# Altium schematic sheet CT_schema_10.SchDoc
size 281 x 153 mm
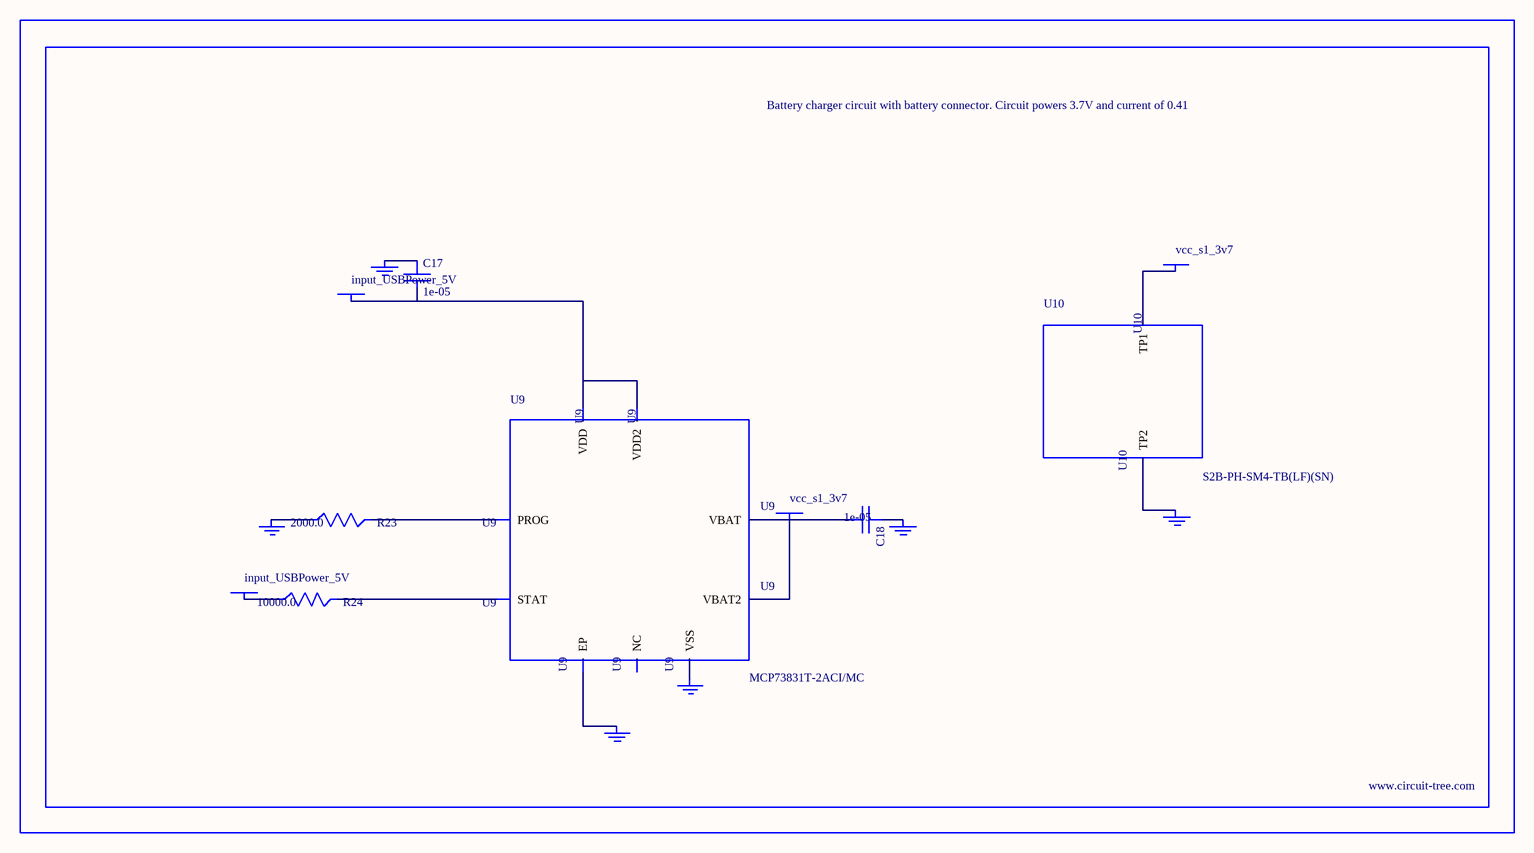
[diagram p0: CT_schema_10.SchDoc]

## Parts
BORDER9  (no value)
C17  1e-05  [C1206]
C18  1e-05  [C1206]
GND_INSTANCE_9_0  (no value)
GND_INSTANCE_9_1  (no value)
GND_INSTANCE_9_2  (no value)
GND_INSTANCE_9_3  (no value)
GND_INSTANCE_9_4  (no value)
GND_INSTANCE_9_5  (no value)
POWER_INSTANCE_9_0  input_USBPower_5V
POWER_INSTANCE_9_1  input_USBPower_5V
POWER_INSTANCE_9_2  vcc_s1_3v7
POWER_INSTANCE_9_3  vcc_s1_3v7
R23  2000.0  [R0603]
R24  10000.0  [R0603]
U9  MCP73831T-2ACI/MC  [DFN8_2X3MC]
U10  S2B-PH-SM4-TB(LF)(SN)  [JST-2-SMD]

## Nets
NetC17_1: C17.1 GND_INSTANCE_9_0.0(GND)
NetC17_2: C17.2 POWER_INSTANCE_9_0.0(PWR) U9.1(VDD) U9.2(VDD2)
NetC18_1: C18.1 GND_INSTANCE_9_1.0(GND)
NetC18_2: C18.2 POWER_INSTANCE_9_2.0(PWR) U9.3(VBAT) U9.4(VBAT2)
NetGND_INSTANCE_9_2_0: GND_INSTANCE_9_2.0(GND) R23.1
NetGND_INSTANCE_9_3_0: GND_INSTANCE_9_3.0(GND) U9.9(EP)
NetGND_INSTANCE_9_4_0: GND_INSTANCE_9_4.0(GND) U9.6(VSS)
NetGND_INSTANCE_9_5_0: GND_INSTANCE_9_5.0(GND) U10.2(TP2)
NetPOWER_INSTANCE_9_1_0: POWER_INSTANCE_9_1.0(PWR) R24.1
NetPOWER_INSTANCE_9_3_0: POWER_INSTANCE_9_3.0(PWR) U10.1(TP1)
NetR23_2: R23.2 U9.8(PROG)
NetR24_2: R24.2 U9.5(STAT)

Not connected (* = marked no-connect by the designer): U9 7(NC)

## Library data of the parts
BORDER9 = BORDER_PAGE9
C17 C18 = C1206C106K3RACTU
GND_INSTANCE_9_0-GND_INSTANCE_9_5 = GND
POWER_INSTANCE_9_0-POWER_INSTANCE_9_3 = PWR
R23 = RC0603JR-072KL
R24 = RC0603JR-0710KL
